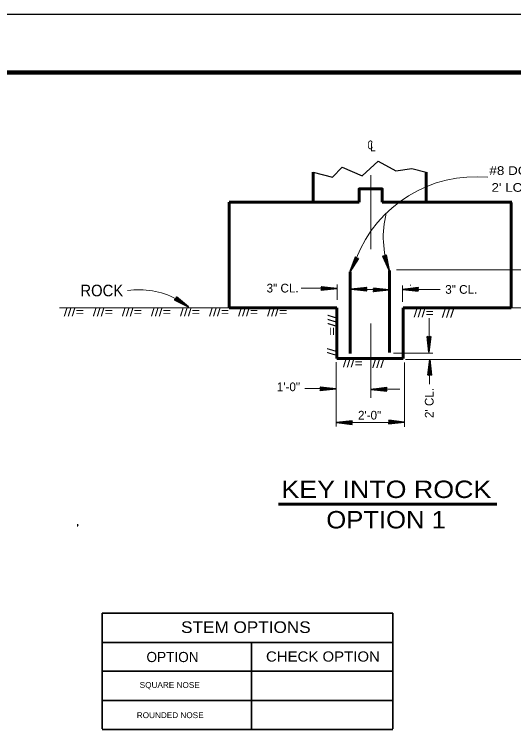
# Model space of a CAD drawing. Extents: x 1.6 to 19.9, y 2.8 to 9.5.
# Drawn here: x 17.696 to 18.367, y 8.58 to 9.545 of the extents above; entities that cross this region are included whole.
import ezdxf
from ezdxf.enums import TextEntityAlignment as Align

# ---------------------------------------------------------------- set-up
doc = ezdxf.new("R2010")
doc.units = 0
doc.header["$LTSCALE"] = 0.0047
doc.linetypes.add('DOT_DASHED', pattern=[7.7, 5, -1.2, 0.3, -1.2])
doc.layers.add('1', color=7, linetype='Continuous', lineweight=35)
doc.layers.add('5', color=7, linetype='Continuous', lineweight=13)

msp = doc.modelspace()

# ---------------------------------------------------------------- linework, layer by layer
at = {"layer": '1', "lineweight": 25}
for p, q in [((19.894917, 9.545083), (16.26675, 9.545083)), ((18.097667, 9.29375), (18.097667, 9.29325)), ((18.249917, 9.29375), (18.249917, 9.29325))]:
    msp.add_line(p, q, dxfattribs=at)
at = {"layer": '1', "lineweight": 60}
for p, q in [((17.985083, 9.2925), (18.1595, 9.2925)), ((17.985083, 9.292333), (17.985083, 9.150583)), ((18.19075, 9.2925), (18.36475, 9.2925)), ((18.364167, 9.291833), (18.364167, 9.15075)), ((18.200667, 9.089833), (18.200667, 9.20025)), ((18.147667, 9.0885), (18.147667, 9.1985)), ((17.98475, 9.15025), (18.12975, 9.15025)), ((18.12975, 9.15025), (18.12975, 9.081917)), ((18.218833, 9.15025), (18.364, 9.15025)), ((18.218833, 9.15025), (18.218833, 9.081917)), ((18.12975, 9.081917), (18.1835, 9.081917)), ((18.218833, 9.081917), (18.165167, 9.081917)), ((18.051083, 8.886), (18.344917, 8.886))]:
    msp.add_line(p, q, dxfattribs=at)
at = {"layer": '1'}
for p, q in [((18.191917, 9.2195), (18.198, 9.20625)), ((18.192167, 9.219667), (18.198167, 9.20625)), ((18.192417, 9.21975), (18.198333, 9.206417)), ((18.192667, 9.219833), (18.198583, 9.2065)), ((18.193667, 9.220583), (18.200167, 9.20075)), ((18.195417, 9.22075), (18.198583, 9.205333)), ((18.1955, 9.22075), (18.198667, 9.205417)), ((18.195667, 9.22075), (18.198917, 9.205417)), ((18.19575, 9.22075), (18.198917, 9.205417)), ((18.195833, 9.22075), (18.199, 9.2055)), ((18.156917, 9.2175), (18.147583, 9.198833)), ((18.158083, 9.2165), (18.149667, 9.20325)), ((18.154917, 9.218), (18.149833, 9.204333)), ((18.158333, 9.216333), (18.149833, 9.20325)), ((18.1585, 9.21625), (18.149917, 9.203083)), ((18.158417, 9.21625), (18.149917, 9.203167)), ((18.155167, 9.218), (18.150083, 9.20425)), ((18.1585, 9.21625), (18.150083, 9.203083)), ((18.155417, 9.217833), (18.15025, 9.204167)), ((18.155583, 9.21775), (18.1505, 9.204083)), ((18.108667, 9.17625), (18.1295, 9.17625)), ((18.108917, 9.174833), (18.1235, 9.1765)), ((18.109, 9.178167), (18.124667, 9.1765)), ((18.109, 9.178083), (18.124667, 9.176417)), ((18.109, 9.178), (18.124583, 9.17625)), ((18.109, 9.17775), (18.124583, 9.176083)), ((18.109, 9.174667), (18.123583, 9.17625)), ((18.109, 9.174417), (18.123583, 9.176)), ((18.109167, 9.17825), (18.124667, 9.176583)), ((18.109167, 9.174167), (18.123667, 9.17575)), ((18.169833, 9.175167), (18.148917, 9.175167)), ((18.169417, 9.17325), (18.153833, 9.175)), ((18.169417, 9.17325), (18.153833, 9.174833)), ((18.169333, 9.173167), (18.153833, 9.17475)), ((18.169417, 9.173583), (18.153917, 9.17525)), ((18.169417, 9.173417), (18.153917, 9.175083)), ((18.169333, 9.17725), (18.154833, 9.175583)), ((18.169417, 9.177), (18.154917, 9.175417)), ((18.169417, 9.17675), (18.154917, 9.175167)), ((18.1695, 9.1765), (18.154917, 9.174833)), ((18.178833, 9.174333), (18.199667, 9.174333)), ((18.179167, 9.17625), (18.194833, 9.174667)), ((18.179167, 9.17625), (18.194833, 9.1745)), ((18.179167, 9.176083), (18.19475, 9.174417)), ((18.179167, 9.175917), (18.19475, 9.17425)), ((18.179167, 9.173), (18.193667, 9.174667)), ((18.179167, 9.17275), (18.193667, 9.174333)), ((18.179167, 9.1725), (18.193667, 9.174083)), ((18.17925, 9.176333), (18.194833, 9.17475)), ((18.17925, 9.17225), (18.193833, 9.173917)), ((18.239167, 9.174833), (18.21825, 9.174833)), ((18.238667, 9.173), (18.223083, 9.174667)), ((18.238667, 9.172833), (18.223083, 9.1745)), ((18.238667, 9.172917), (18.223083, 9.1745)), ((18.238667, 9.17325), (18.223167, 9.175)), ((18.238667, 9.173083), (18.223167, 9.17475)), ((18.238667, 9.176917), (18.224167, 9.17525)), ((18.238667, 9.176667), (18.224167, 9.175083)), ((18.238667, 9.176417), (18.224167, 9.174833)), ((18.238833, 9.17625), (18.22425, 9.1745)), ((17.91225, 9.161583), (17.925167, 9.154667)), ((17.912417, 9.161833), (17.925167, 9.154833)), ((17.91275, 9.163083), (17.930083, 9.15125)), ((17.914, 9.164167), (17.925917, 9.153917)), ((17.914167, 9.164333), (17.926, 9.154083)), ((17.91425, 9.1645), (17.926167, 9.15425)), ((17.91425, 9.164417), (17.926167, 9.154167)), ((17.914333, 9.1645), (17.926167, 9.154333)), ((17.912083, 9.16125), (17.924917, 9.15425)), ((17.912167, 9.161333), (17.925083, 9.1545)), ((18.251417, 9.111), (18.253083, 9.096417)), ((18.251667, 9.111), (18.25325, 9.0965)), ((18.251917, 9.111), (18.2535, 9.0965)), ((18.252167, 9.111083), (18.253833, 9.096583)), ((18.255083, 9.111), (18.253417, 9.0955)), ((18.2535, 9.111417), (18.2535, 9.090583)), ((18.25525, 9.111), (18.253583, 9.0955)), ((18.255417, 9.111), (18.253667, 9.095417)), ((18.255417, 9.111), (18.253833, 9.095417)), ((18.2555, 9.111), (18.253917, 9.095417)), ((18.252417, 9.060083), (18.254167, 9.075667)), ((18.252583, 9.06), (18.254167, 9.075667)), ((18.252667, 9.06), (18.25425, 9.075667)), ((18.252667, 9.06), (18.254417, 9.075583)), ((18.252917, 9.06), (18.254583, 9.075583)), ((18.2545, 9.059667), (18.2545, 9.0805)), ((18.2565, 9.060083), (18.254917, 9.074667)), ((18.255833, 9.06), (18.254167, 9.0745)), ((18.256083, 9.06), (18.2545, 9.0745)), ((18.256333, 9.06), (18.25475, 9.0745)), ((18.107417, 9.041083), (18.12825, 9.041083)), ((18.107667, 9.03975), (18.12225, 9.041417)), ((18.10775, 9.043083), (18.123417, 9.041417)), ((18.10775, 9.043), (18.123417, 9.041333)), ((18.10775, 9.042917), (18.123333, 9.04125)), ((18.10775, 9.042667), (18.123333, 9.041)), ((18.10775, 9.0395), (18.122333, 9.041083)), ((18.10775, 9.039333), (18.122333, 9.040917)), ((18.107917, 9.043167), (18.123417, 9.0415)), ((18.107917, 9.039083), (18.122417, 9.04075)), ((18.19675, 9.040333), (18.175917, 9.040333)), ((18.196417, 9.0385), (18.18075, 9.040083)), ((18.196333, 9.03825), (18.18075, 9.04)), ((18.196417, 9.038417), (18.18075, 9.04)), ((18.196417, 9.03875), (18.180833, 9.040417)), ((18.196417, 9.0385), (18.180833, 9.04025)), ((18.196333, 9.042333), (18.18175, 9.04075)), ((18.196417, 9.042167), (18.181833, 9.040583)), ((18.196417, 9.041917), (18.181833, 9.040333)), ((18.196417, 9.041667), (18.181917, 9.04)), ((18.149583, 8.997583), (18.135083, 8.996)), ((18.149667, 8.997333), (18.135167, 8.99575)), ((18.19975, 8.99825), (18.215417, 8.996667)), ((18.19975, 8.99825), (18.215417, 8.996583)), ((18.19975, 8.998167), (18.21525, 8.996417)), ((18.19975, 8.997917), (18.21525, 8.99625)), ((18.199833, 8.998417), (18.215417, 8.99675)), ((18.150083, 8.995583), (18.129167, 8.995583)), ((18.149667, 8.99375), (18.134, 8.995333)), ((18.149667, 8.993583), (18.134, 8.99525)), ((18.149583, 8.9935), (18.134, 8.995167)), ((18.149667, 8.994), (18.134167, 8.995667)), ((18.149667, 8.99375), (18.134167, 8.9955)), ((18.149667, 8.997167), (18.135167, 8.995583)), ((18.14975, 8.996917), (18.135167, 8.99525)), ((18.199333, 8.996333), (18.220167, 8.996333)), ((18.199667, 8.995), (18.214167, 8.996667)), ((18.19975, 8.99475), (18.21425, 8.996333)), ((18.19975, 8.9945), (18.21425, 8.996083)), ((18.199833, 8.994333), (18.214333, 8.996)), ((17.814083, 8.739), (18.20475, 8.739)), ((17.814083, 8.583333), (17.814083, 8.739)), ((18.20475, 8.739), (18.20475, 8.583333)), ((17.814083, 8.699917), (18.20475, 8.699917)), ((18.015, 8.583917), (18.015, 8.699667)), ((17.814083, 8.660917), (18.20475, 8.660917)), ((17.814083, 8.621833), (18.20475, 8.621833)), ((18.20475, 8.58275), (17.814083, 8.58275))]:
    msp.add_line(p, q, dxfattribs=at)
at = {"layer": '1', "lineweight": 13}
for p, q in [((18.209667, 9.20125), (18.411667, 9.20125)), ((18.129917, 9.160667), (18.129917, 9.181667)), ((18.228833, 9.180917), (18.228833, 9.18)), ((18.11675, 9.176583), (18.081667, 9.176583)), ((18.153333, 9.174833), (18.197, 9.174833)), ((18.21775, 9.15825), (18.21775, 9.18025)), ((18.23325, 9.17475), (18.268417, 9.17475)), ((18.358167, 9.15025), (18.323583, 9.15025)), ((18.253833, 9.136083), (18.253833, 9.101)), ((18.205667, 9.089167), (18.258667, 9.089167)), ((18.128667, 9.077), (18.128667, 8.990333)), ((18.220417, 9.07675), (18.220417, 8.99)), ((18.22175, 9.0805), (18.412583, 9.0805)), ((18.254167, 9.081083), (18.254167, 9.0475)), ((18.086667, 9.041417), (18.122333, 9.041417)), ((18.1785, 9.040417), (18.214167, 9.040417)), ((18.136917, 8.995667), (18.212667, 8.995667))]:
    msp.add_line(p, q, dxfattribs=at)
at = {"layer": '1', "lineweight": 106}
msp.add_lwpolyline([(19.823, 7.367), (19.823, 9.467), (16.423, 9.467), (16.423, 7.367)], dxfattribs=at)
at = {"layer": '1', "lineweight": 60}
for points in [[(18.175167, 9.31025), (18.1595, 9.31025), (18.1595, 9.292333)], [(18.175167, 9.31025), (18.19075, 9.31025), (18.19075, 9.292333)]]:
    msp.add_lwpolyline(points, dxfattribs=at)
at = {"layer": '1'}
for points in [[(18.195917, 9.22125), (18.200167, 9.20075), (18.1915, 9.219833), (18.194167, 9.2195)], [(18.158917, 9.2165), (18.147583, 9.198833), (18.154833, 9.2185), (18.156417, 9.2165)], [(18.108667, 9.1785), (18.1295, 9.17625), (18.108667, 9.173833), (18.10975, 9.17625)], [(18.178833, 9.176667), (18.199667, 9.174333), (18.178833, 9.172), (18.179917, 9.174333)], [(18.239167, 9.1725), (18.21825, 9.174833), (18.239167, 9.17725), (18.238, 9.174833)], [(18.237667, 9.1745), (18.228417, 9.1745), (18.228417, 9.17475), (18.230167, 9.1745)], [(17.914167, 9.165), (17.930083, 9.15125), (17.9115, 9.161083), (17.913833, 9.1625)], [(17.914167, 9.1625), (17.921833, 9.15725), (17.921667, 9.157167), (17.92025, 9.15825), (17.914167, 9.162583), (17.91925, 9.159417), (17.914167, 9.163), (17.917917, 9.160667), (17.914167, 9.1635), (17.919833, 9.158917), (17.92725, 9.15325), (17.925417, 9.154), (17.927667, 9.15275), (17.913917, 9.162167), (17.917667, 9.159083), (17.9135, 9.162), (17.922667, 9.156583), (17.913167, 9.161667)], [(18.255833, 9.111417), (18.2535, 9.090583), (18.251167, 9.111417), (18.2535, 9.110333)], [(18.252167, 9.059667), (18.2545, 9.0805), (18.256833, 9.059667), (18.2545, 9.06075)], [(18.254167, 9.061), (18.254167, 9.070333), (18.254333, 9.070333), (18.254167, 9.0685)], [(18.107417, 9.0435), (18.12825, 9.041083), (18.107417, 9.03875), (18.1085, 9.041083)], [(18.19675, 9.038), (18.175917, 9.040333), (18.19675, 9.042667), (18.195667, 9.040333)], [(18.195417, 9.04), (18.186083, 9.04), (18.186083, 9.040167), (18.187917, 9.04)], [(18.150083, 8.99325), (18.129167, 8.995583), (18.150083, 8.997917), (18.148917, 8.995583)], [(18.199333, 8.99875), (18.220167, 8.996333), (18.199333, 8.994), (18.200417, 8.996333)]]:
    msp.add_lwpolyline(points, close=True, dxfattribs=at)
for points in [[(18.194417, 9.219333), (18.197417, 9.2105), (18.197167, 9.2105), (18.19675, 9.21225), (18.1945, 9.219333), (18.196667, 9.21375), (18.19475, 9.21975), (18.196167, 9.215583), (18.195083, 9.22), (18.19675, 9.213), (18.19925, 9.204083), (18.198167, 9.20575), (18.199167, 9.203417), (18.193917, 9.219167), (18.195167, 9.2145), (18.193583, 9.219333), (18.197583, 9.2095), (18.193167, 9.21925), (18.194333, 9.21925), (18.1955, 9.220583), (18.195417, 9.22), (18.194667, 9.219333), (18.195083, 9.218917), (18.195583, 9.2195), (18.194167, 9.219333), (18.193083, 9.2195), (18.192, 9.2195)], [(18.1565, 9.216083), (18.152417, 9.20775), (18.15225, 9.207917), (18.153167, 9.2095), (18.156667, 9.216083), (18.154167, 9.210667), (18.157, 9.21625), (18.155167, 9.21225), (18.157417, 9.21625), (18.153667, 9.21), (18.14925, 9.201917), (18.149667, 9.203833), (18.148667, 9.201417), (18.156083, 9.216333), (18.153667, 9.212167), (18.155917, 9.21675), (18.151833, 9.206917), (18.155583, 9.217), (18.156417, 9.216083), (18.158167, 9.21625), (18.157667, 9.216), (18.156667, 9.216), (18.156667, 9.215417), (18.157417, 9.215417), (18.156333, 9.216333), (18.155667, 9.217167), (18.154917, 9.218)], [(18.110083, 9.1765), (18.119333, 9.176583), (18.119333, 9.176333), (18.117583, 9.1765), (18.110083, 9.176583), (18.116083, 9.176833), (18.109833, 9.176917), (18.114167, 9.177), (18.109583, 9.17725), (18.11675, 9.17675), (18.126083, 9.176333), (18.124167, 9.17575), (18.126667, 9.176), (18.110083, 9.176), (18.114917, 9.175667), (18.109833, 9.175667), (18.120417, 9.176417), (18.109667, 9.17525), (18.110167, 9.176417), (18.109167, 9.177917), (18.109667, 9.177583), (18.110167, 9.17675), (18.110583, 9.177), (18.11025, 9.177583), (18.109917, 9.17625), (18.1095, 9.17525), (18.109167, 9.17425)], [(18.169833, 9.172833), (18.148917, 9.175167), (18.169833, 9.1775)], [(18.168417, 9.174833), (18.159167, 9.17475), (18.159167, 9.175), (18.160917, 9.174833), (18.168417, 9.17475), (18.162417, 9.1745), (18.168667, 9.1745), (18.16425, 9.174333), (18.168917, 9.174083), (18.161667, 9.174667), (18.152417, 9.175), (18.154333, 9.175583), (18.15175, 9.175333), (18.168417, 9.175417), (18.163583, 9.17575), (18.168667, 9.17575), (18.158, 9.175), (18.168833, 9.176083)], [(18.168833, 9.176083), (18.168333, 9.175), (18.16925, 9.1735), (18.168833, 9.17375), (18.168333, 9.174667), (18.167917, 9.174417), (18.168167, 9.17375), (18.1685, 9.175167), (18.168917, 9.176083), (18.169333, 9.177167)], [(18.169833, 9.1775), (18.168667, 9.175167), (18.169833, 9.172833)], [(18.180167, 9.174667), (18.1895, 9.17475), (18.1895, 9.1745), (18.187667, 9.174667), (18.180167, 9.17475), (18.186167, 9.175), (18.179917, 9.175), (18.184333, 9.175167), (18.17975, 9.175417), (18.186917, 9.174833), (18.196167, 9.1745), (18.19425, 9.173917), (18.196833, 9.174167), (18.180167, 9.174083), (18.185083, 9.17375), (18.179917, 9.17375), (18.190583, 9.1745), (18.179833, 9.173417), (18.18025, 9.1745), (18.179333, 9.176), (18.179833, 9.17575), (18.18025, 9.174833), (18.18075, 9.175083), (18.180417, 9.17575), (18.180167, 9.174333), (18.179667, 9.173417), (18.17925, 9.172333)], [(18.237667, 9.1745), (18.231667, 9.17425), (18.237917, 9.174167), (18.233583, 9.174), (18.238167, 9.17375), (18.231, 9.174333), (18.221667, 9.17475), (18.223667, 9.17525), (18.221083, 9.175), (18.237667, 9.175083), (18.232917, 9.175417), (18.237917, 9.175417), (18.227333, 9.174667), (18.238083, 9.17575), (18.237667, 9.174667), (18.238583, 9.173167), (18.238083, 9.1735), (18.237667, 9.174333), (18.237167, 9.174083), (18.237417, 9.1735), (18.23775, 9.174833), (18.23825, 9.17575), (18.238667, 9.176833)], [(17.914167, 9.1625), (17.91425, 9.164167), (17.9145, 9.163583), (17.914333, 9.162667), (17.914917, 9.162583), (17.914917, 9.16325), (17.913917, 9.16225), (17.913, 9.161833), (17.912083, 9.16125)], [(18.253833, 9.11), (18.253917, 9.10075), (18.253667, 9.10075), (18.253833, 9.1025), (18.253917, 9.11), (18.254167, 9.104), (18.254167, 9.11025), (18.254333, 9.105917), (18.254583, 9.1105), (18.254, 9.10325), (18.253667, 9.094), (18.253083, 9.096), (18.253333, 9.093417), (18.25325, 9.11), (18.252917, 9.105167), (18.252917, 9.11025), (18.253667, 9.099667), (18.252583, 9.110417), (18.253667, 9.11), (18.255167, 9.110917), (18.254917, 9.110417), (18.254, 9.11), (18.25425, 9.1095), (18.254917, 9.10975), (18.2535, 9.110083), (18.252583, 9.110583), (18.2515, 9.111)], [(18.254167, 9.061), (18.253917, 9.067), (18.253833, 9.06075), (18.253667, 9.065167), (18.253417, 9.060583), (18.253917, 9.06775), (18.254333, 9.077), (18.254917, 9.075083), (18.254667, 9.077667), (18.25475, 9.061), (18.255083, 9.065917), (18.255083, 9.06075), (18.25425, 9.071417), (18.255417, 9.060667), (18.25425, 9.061083), (18.25275, 9.060167), (18.253083, 9.060667), (18.253917, 9.061083), (18.253667, 9.061583), (18.253083, 9.06125), (18.2545, 9.061), (18.255417, 9.0605), (18.256417, 9.060083)], [(18.108833, 9.041417), (18.118083, 9.0415), (18.118083, 9.04125), (18.116333, 9.041417), (18.108833, 9.0415), (18.114833, 9.04175), (18.108583, 9.041833), (18.112917, 9.042), (18.108333, 9.04225), (18.1155, 9.041667), (18.124833, 9.04125), (18.122917, 9.04075), (18.125417, 9.041), (18.108833, 9.040917), (18.113667, 9.040583), (18.108583, 9.040583), (18.119167, 9.041333), (18.108417, 9.040167), (18.108917, 9.041333), (18.107917, 9.042833), (18.108417, 9.0425), (18.108917, 9.041667), (18.109333, 9.041917), (18.109, 9.0425), (18.108667, 9.041083), (18.10825, 9.040167), (18.107917, 9.039167)], [(18.195417, 9.04), (18.189333, 9.03975), (18.195583, 9.039667), (18.191167, 9.0395), (18.195833, 9.03925), (18.188667, 9.03975), (18.179333, 9.040167), (18.181333, 9.04075), (18.178667, 9.0405), (18.195417, 9.040583), (18.1905, 9.040917), (18.195583, 9.040917), (18.184917, 9.040083), (18.19575, 9.04125), (18.19525, 9.040083), (18.196167, 9.038583), (18.19575, 9.038917), (18.19525, 9.03975), (18.194833, 9.0395), (18.195167, 9.038917), (18.195417, 9.040333), (18.195917, 9.04125), (18.196333, 9.04225)], [(18.148667, 8.99525), (18.139333, 8.995167), (18.139333, 8.995417), (18.141167, 8.99525), (18.148667, 8.995167), (18.142667, 8.995), (18.148917, 8.994833), (18.1445, 8.99475), (18.149167, 8.9945), (18.141917, 8.995), (18.132667, 8.995417), (18.134583, 8.996), (18.132, 8.99575), (18.148667, 8.99575), (18.143833, 8.996083), (18.148917, 8.996083), (18.13825, 8.995333), (18.149, 8.9965), (18.148583, 8.995333), (18.1495, 8.993833), (18.149, 8.994167), (18.148583, 8.995), (18.148083, 8.99475), (18.148417, 8.994167), (18.148667, 8.995583), (18.149167, 8.9965), (18.149583, 8.9975)], [(18.20075, 8.996667), (18.210083, 8.99675), (18.210083, 8.9965), (18.20825, 8.996667), (18.20075, 8.99675), (18.20675, 8.997), (18.2005, 8.997), (18.204917, 8.99725), (18.20025, 8.9975), (18.207417, 8.996917), (18.21675, 8.9965), (18.214833, 8.996), (18.217417, 8.99625), (18.20075, 8.996083), (18.205583, 8.99575), (18.2005, 8.99575), (18.211167, 8.996583), (18.200417, 8.995417), (18.200833, 8.996583), (18.199917, 8.998083), (18.200417, 8.99775), (18.200833, 8.996917), (18.201333, 8.997167), (18.201, 8.99775), (18.200667, 8.996333), (18.200167, 8.995417), (18.199833, 8.994417)]]:
    msp.add_lwpolyline(points, dxfattribs=at)
at = {"layer": '1', "lineweight": 13}
msp.add_lwpolyline([(17.781167, 8.858833), (17.781167, 8.855917), (17.781833, 8.857833), (17.781, 8.857833)], dxfattribs=at)
at = {"layer": '5', "linetype": 'DOT_DASHED'}
msp.add_line((18.175167, 9.028833), (18.175167, 9.388417), dxfattribs=at)
at = {"layer": '5', "lineweight": 60}
for p, q in [((18.097667, 9.29375), (18.097667, 9.33275)), ((18.249917, 9.29375), (18.249917, 9.33275))]:
    msp.add_line(p, q, dxfattribs=at)
at = {"layer": '5'}
for p, q in [((17.756667, 9.15025), (18.069167, 9.15025)), ((18.364, 9.15025), (18.442167, 9.15025))]:
    msp.add_line(p, q, dxfattribs=at)
at = {"layer": '5', "lineweight": 25}
msp.add_lwpolyline([(18.097667, 9.33275), (18.123833, 9.326083), (18.137, 9.339417), (18.163583, 9.32775), (18.185167, 9.347667), (18.209167, 9.334417), (18.230667, 9.337667), (18.249917, 9.33275)], dxfattribs=at)
at = {"layer": '5'}
for centre, radius, start, end in [((18.316593, 9.154044), 0.17251, 84.59466, 158.75005), ((18.320732, 9.245653), 0.128651, 165.73713, 200.44784), ((17.863082, 9.063366), 0.111141, 62.95011, 97.63658)]:
    msp.add_arc(centre, radius, start, end, dxfattribs=at)

# ---------------------------------------------------------------- texts
at = {"layer": '1', "width": 1.1}
msp.add_text('STEM OPTIONS', height=0.01567, dxfattribs=at).set_placement((18.007375, 8.7125), align=Align.CENTER)
at = {"layer": '1'}
msp.add_text('OPTION', height=0.01367, dxfattribs=at).set_placement((17.87375, 8.673333))
for s, height, width, p in [('CHECK OPTION', 0.01367, 1.1, (18.034417, 8.674)), ('SQUARE NOSE', 0.007833, 1.05, (17.864667, 8.638667)), ('ROUNDED NOSE', 0.007833, 1.05, (17.86075, 8.597917))]:
    msp.add_text(s, height=height, dxfattribs=dict(at, width=width)).set_placement(p)
at = {"layer": '5'}
for s, height, width, p in [('C', 0.01175, 0.65, (18.174542, 9.3635)), ('L', 0.01175, 0.85, (18.178208, 9.36075)), ('///=', 0.01142, 1.25, (17.776083, 9.138833)), ('///=', 0.01142, 1.25, (17.815125, 9.138833)), ('///=', 0.01142, 1.25, (17.854125, 9.138833)), ('///=', 0.01142, 1.25, (17.893167, 9.138833)), ('///=', 0.01142, 1.25, (17.93225, 9.138833)), ('///=', 0.01142, 1.25, (17.971333, 9.138833)), ('///=', 0.01142, 1.25, (18.010375, 9.138833)), ('///=', 0.01142, 1.25, (18.049417, 9.138833)), ('///=', 0.01142, 1.25, (18.2465, 9.137667)), ('///=', 0.01133, 1.25, (18.151083, 9.07)), ('OPTION 1', 0.02342, 1.1, (18.195875, 8.85325))]:
    msp.add_text(s, height=height, dxfattribs=dict(at, width=width)).set_placement(p, align=Align.CENTER)
for s, height, width, p in [('#8 DOWELS SPACED @', 0.01175, 1.15, (18.33475, 9.328917)), ("2' LONGITUDINAL", 0.01167, 1.15, (18.337583, 9.30625)), ('ROCK', 0.01567, 0.95, (17.784917, 9.165583)), ('///', 0.01167, 1.3, (18.270583, 9.136833)), ('///', 0.01175, 1.25, (18.177167, 9.0695)), ('KEY INTO ROCK', 0.02342, 1.15, (18.055167, 8.894167))]:
    msp.add_text(s, height=height, dxfattribs=dict(at, width=width)).set_placement(p)
for p in [(18.078333, 9.17075), (18.3185, 9.169)]:
    msp.add_text('3" CL.', height=0.01175, dxfattribs=at).set_placement(p, align=Align.RIGHT)
at = {"layer": '5', "width": 1.25}
msp.add_text('///=', height=0.01192, rotation=270, dxfattribs=at).set_placement((18.117417, 9.126833), align=Align.CENTER)
at = {"layer": '5', "width": 1.2}
msp.add_text('//', height=0.01167, rotation=90, dxfattribs=at).set_placement((18.128917, 9.0855))
at = {"layer": '5'}
for s, height, p in [('1\'-0"', 0.01175, (18.064583, 9.037917)), ('2\'-0"', 0.01167, (18.173667, 8.99975))]:
    msp.add_text(s, height=height, dxfattribs=at).set_placement(p, align=Align.CENTER)
msp.add_text("2' CL.", height=0.01175, rotation=90, dxfattribs=at).set_placement((18.25975, 9.042333), align=Align.RIGHT)

doc.saveas('drawing.dxf')
